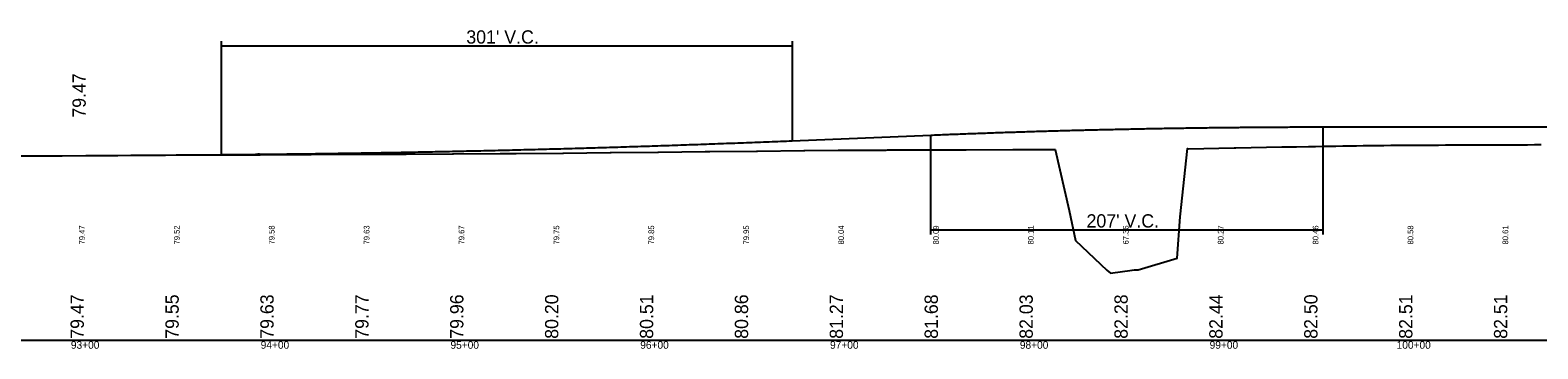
# Model space of a CAD drawing. Extents: x 1592 to 6065, y -1942 to -1437.
# Drawn here: x 3390 to 4185, y -1942 to -1774 of the extents above; entities that cross this region are included whole.
import ezdxf

# ---------------------------------------------------------------- set-up
doc = ezdxf.new("R2010")
doc.units = 0
for name, color, linetype in [('Default', 7, 'Continuous'), ('RD_DDB_Profile_EX', 7, 'Continuous'), ('RD_DDB_Profile_Lbl', 7, 'Continuous'), ('RD_DDB_Profile_PR', 7, 'Continuous'), ('RD_DDB_StaTX', 7, 'Continuous'), ('RD_DDB_StripGrade', 7, 'Continuous'), ('RD_DDB_VCLbl', 7, 'Continuous'), ('RD_GPK_Profile_Cell', 7, 'Continuous')]:
    doc.layers.add(name, color=color, linetype=linetype)

msp = doc.modelspace()

# ---------------------------------------------------------------- linework, layer by layer
at = {"layer": 'Default'}
for p, q in [((3510.88, -1839.51), (3510.88, -1838.67)), ((3555.94, -1839.27), (3555.94, -1838.44))]:
    msp.add_line(p, q, dxfattribs=at)
at = {"layer": 'RD_DDB_Profile_EX'}
for points in [[(4000.86, -1836.31), (4024.9, -1835.86), (4025.82, -1835.85), (4049.94, -1835.4), (4050.55, -1835.39), (4057.68, -1835.26), (4064.07, -1835.14), (4067.68, -1835.08), (4071.28, -1835.01), (4074.03, -1834.97), (4074.89, -1834.95), (4078.49, -1834.91), (4082.1, -1834.86), (4082.66, -1834.85), (4082.99, -1834.84), (4085.7, -1834.81), (4089.31, -1834.76), (4092.91, -1834.71), (4096.52, -1834.67), (4100.12, -1834.62), (4103.73, -1834.58), (4107.34, -1834.54), (4107.64, -1834.54), (4107.95, -1834.53), (4110.94, -1834.5), (4114.55, -1834.46), (4116.4, -1834.44), (4118.15, -1834.43), (4121.76, -1834.41), (4125.36, -1834.4), (4128.97, -1834.38), (4132.57, -1834.37), (4136.18, -1834.35), (4139.78, -1834.34), (4140.42, -1834.34), (4141.41, -1834.32), (4143.39, -1834.31), (4146.99, -1834.3), (4150.6, -1834.29), (4154.2, -1834.29), (4157.81, -1834.29), (4161.41, -1834.28), (4165.02, -1834.28), (4165.81, -1834.28), (4166.52, -1834.27), (4168.63, -1834.27), (4172.23, -1834.28), (4173.07, -1834.28), (4173.41, -1834.27), (4175.84, -1834.25), (4179.44, -1834.22), (4183.05, -1834.19), (4186.65, -1834.16)], [(3382.18, -1840.12), (3406.79, -1840.02), (3407.3, -1840.02), (3431.96, -1839.93), (3436.7, -1839.91), (3460.99, -1839.78), (3461.7, -1839.77), (3485.93, -1839.64), (3486.7, -1839.64), (3510.88, -1839.51), (3511.7, -1839.5), (3535.82, -1839.37), (3536.71, -1839.37), (3538.58, -1839.35), (3562.8, -1839.24), (3563.58, -1839.24), (3587.92, -1839.12), (3588.58, -1839.12), (3613.03, -1839), (3613.58, -1839), (3638.14, -1838.88), (3638.58, -1838.88), (3646.52, -1838.84), (3671.12, -1838.59), (3671.52, -1838.59), (3696.13, -1838.34), (3696.52, -1838.33), (3721.14, -1838.08), (3721.51, -1838.08), (3746.15, -1837.83), (3746.51, -1837.82), (3748.66, -1837.8), (3773.21, -1837.56), (3773.66, -1837.56), (3798.12, -1837.32), (3798.66, -1837.33), (3816.12, -1837.16), (3816.54, -1837.16), (3817.13, -1837.15), (3841.53, -1837.01), (3842.18, -1837), (3858.7, -1836.9), (3882.87, -1836.85), (3883.7, -1836.85), (3908.19, -1836.8), (3908.87, -1836.81), (3930.62, -1836.74), (3937.96, -1868.87), (3941.34, -1884.75), (3957.74, -1900.4), (3959.74, -1901.94), (3971.13, -1900.35), (3972.23, -1900.23), (3974.31, -1900.13), (3994.86, -1893.99), (3996.39, -1872.3), (4000.28, -1836.29), (4000.86, -1836.31)]]:
    msp.add_lwpolyline(points, dxfattribs=at)
at = {"layer": 'RD_DDB_Profile_PR'}
for p, q in [((4071.68, -1824.84), (4230.39, -1824.72)), ((3791.91, -1832.14), (3864.95, -1829.14)), ((3419.75, -1839.97), (3491.13, -1839.44))]:
    msp.add_line(p, q, dxfattribs=at)
for points in [[(3864.95, -1829.14), (3869.08, -1828.98), (3873.22, -1828.81), (3877.35, -1828.65), (3881.48, -1828.49), (3885.62, -1828.34), (3889.75, -1828.19), (3893.89, -1828.04), (3898.02, -1827.9), (3902.16, -1827.75), (3906.29, -1827.62), (3910.43, -1827.48), (3914.56, -1827.35), (3918.7, -1827.22), (3922.83, -1827.1), (3926.97, -1826.98), (3931.1, -1826.86), (3935.23, -1826.75), (3939.37, -1826.63), (3943.5, -1826.53), (3947.64, -1826.42), (3951.77, -1826.32), (3955.91, -1826.22), (3960.04, -1826.13), (3964.18, -1826.04), (3968.31, -1825.95), (3972.45, -1825.87), (3976.58, -1825.78), (3980.71, -1825.71), (3984.85, -1825.63), (3988.98, -1825.56), (3993.12, -1825.49), (3997.25, -1825.43), (4001.39, -1825.37), (4005.52, -1825.31), (4009.66, -1825.25), (4013.79, -1825.2), (4017.93, -1825.16), (4022.06, -1825.11), (4026.2, -1825.07), (4030.33, -1825.03), (4034.46, -1825), (4038.6, -1824.97), (4042.73, -1824.94), (4046.87, -1824.91), (4051, -1824.89), (4055.14, -1824.87), (4059.27, -1824.86), (4063.41, -1824.85), (4067.54, -1824.84), (4071.68, -1824.84)], [(3491.13, -1839.44), (3497.15, -1839.39), (3503.16, -1839.34), (3509.18, -1839.28), (3515.19, -1839.22), (3521.21, -1839.16), (3527.22, -1839.09), (3533.24, -1839.02), (3539.26, -1838.94), (3545.27, -1838.86), (3551.29, -1838.78), (3557.3, -1838.69), (3563.32, -1838.6), (3569.33, -1838.51), (3575.35, -1838.41), (3581.37, -1838.3), (3587.38, -1838.19), (3593.4, -1838.08), (3599.41, -1837.97), (3605.43, -1837.85), (3611.44, -1837.72), (3617.46, -1837.59), (3623.47, -1837.46), (3629.49, -1837.33), (3635.51, -1837.19), (3641.52, -1837.04), (3647.54, -1836.9), (3653.55, -1836.74), (3659.57, -1836.59), (3665.58, -1836.43), (3671.6, -1836.26), (3677.61, -1836.1), (3683.63, -1835.92), (3689.65, -1835.75), (3695.66, -1835.57), (3701.68, -1835.38), (3707.69, -1835.19), (3713.71, -1835), (3719.72, -1834.81), (3725.74, -1834.61), (3731.75, -1834.4), (3737.77, -1834.19), (3743.79, -1833.98), (3749.8, -1833.76), (3755.82, -1833.54), (3761.83, -1833.32), (3767.85, -1833.09), (3773.86, -1832.86), (3779.88, -1832.62), (3785.9, -1832.38), (3791.91, -1832.14)]]:
    msp.add_spline(points, degree=3, dxfattribs=at)
at = {"layer": 'RD_DDB_VCLbl'}
for p, q in [((3491.13, -1779.64), (3491.13, -1839.44)), ((3491.13, -1782.14), (3791.91, -1782.14)), ((3791.91, -1779.64), (3791.91, -1832.14)), ((4071.68, -1881.64), (4071.68, -1824.84)), ((3864.95, -1881.64), (3864.95, -1829.14)), ((3864.95, -1879.14), (4071.68, -1879.14))]:
    msp.add_line(p, q, dxfattribs=at)
at = {"layer": 'RD_GPK_Profile_Cell'}
msp.add_line((1619.75, -1937.33), (6065.43, -1937.33), dxfattribs=at)

# ---------------------------------------------------------------- texts
at = {"layer": 'RD_DDB_Profile_Lbl'}
msp.add_text('79.47', height=7, rotation=90, dxfattribs=at).set_placement((3419.75, -1819.97))
at = {"layer": 'RD_DDB_StaTX'}
for s, p in [('93+00', (3411.93, -1941.83)), ('94+00', (3511.93, -1941.83)), ('95+00', (3611.93, -1941.83)), ('96+00', (3711.93, -1941.83)), ('97+00', (3811.93, -1941.83)), ('98+00', (3911.93, -1941.83)), ('99+00', (4011.93, -1941.83)), ('100+00', (4110.46, -1941.83))]:
    msp.add_text(s, height=4, dxfattribs=at).set_placement(p)
at = {"layer": 'RD_DDB_StripGrade'}
for s, height, p in [('79.47', 3, (3419.25, -1886.83)), ('79.52', 3, (3469.25, -1886.83)), ('79.58', 3, (3519.25, -1886.83)), ('79.63', 3, (3569.25, -1886.83)), ('79.67', 3, (3619.25, -1886.83)), ('79.75', 3, (3669.25, -1886.83)), ('79.85', 3, (3719.25, -1886.83)), ('79.95', 3, (3769.25, -1886.83)), ('80.04', 3, (3819.25, -1886.83)), ('80.09', 3, (3869.25, -1886.83)), ('80.11', 3, (3919.25, -1886.83)), ('67.36', 3, (3969.25, -1886.83)), ('80.27', 3, (4019.25, -1886.83)), ('80.46', 3, (4069.25, -1886.83)), ('80.58', 3, (4119.25, -1886.83)), ('80.61', 3, (4169.25, -1886.83)), ('79.47', 7, (3418.75, -1936.58)), ('79.55', 7, (3468.75, -1936.58)), ('79.63', 7, (3518.75, -1936.58)), ('79.77', 7, (3568.75, -1936.58)), ('79.96', 7, (3618.75, -1936.58)), ('80.20', 7, (3668.75, -1936.58)), ('80.51', 7, (3718.75, -1936.58)), ('80.86', 7, (3768.75, -1936.58)), ('81.27', 7, (3818.75, -1936.58)), ('81.68', 7, (3868.75, -1936.58)), ('82.03', 7, (3918.75, -1936.58)), ('82.28', 7, (3968.75, -1936.58)), ('82.44', 7, (4018.75, -1936.58)), ('82.50', 7, (4068.75, -1936.58)), ('82.51', 7, (4118.75, -1936.58)), ('82.51', 7, (4168.75, -1936.58))]:
    msp.add_text(s, height=height, rotation=90, dxfattribs=at).set_placement(p)
at = {"layer": 'RD_DDB_VCLbl'}
for s, p in [("301' V.C.", (3620.27, -1780.89)), ("207' V.C.", (3947.06, -1877.89))]:
    msp.add_text(s, height=7, dxfattribs=at).set_placement(p)

doc.saveas('drawing.dxf')
